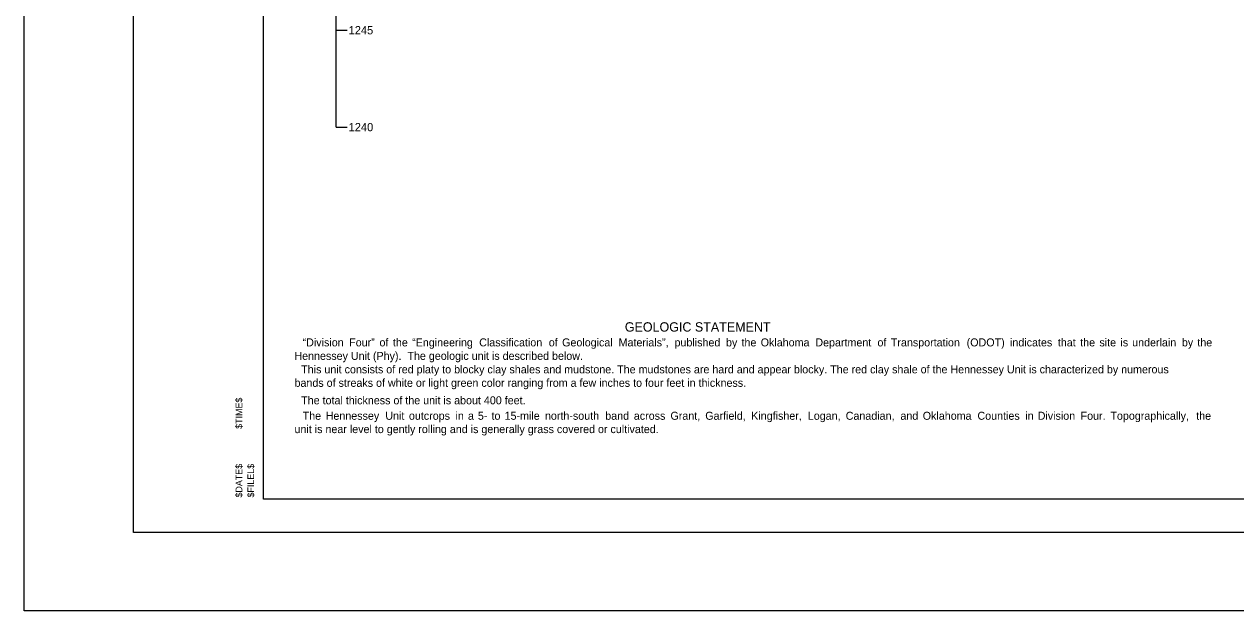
# Model space of a CAD drawing. Extents: x 7 to 126, y 24 to 56.
# Drawn here: x 48.3 to 66.46, y 29.97 to 38.77 of the extents above; entities that cross this region are included whole.
import ezdxf

# ---------------------------------------------------------------- set-up
doc = ezdxf.new("R2010")
doc.units = 0
for name, color, linetype in [('SHT_Plot_Shape_Full', 7, 'Continuous'), ('SHT_Plot_Shape_Half', 7, 'Continuous'), ('SHT_Plot_Stamp', 7, 'Continuous'), ('SHT_Sheet_Border', 7, 'Continuous'), ('Text', 7, 'Continuous')]:
    doc.layers.add(name, color=color, linetype=linetype)

# ---------------------------------------------------------------- blocks, each defined once
blk = doc.blocks.new('Stamp_Plot_Stamp')
at = {"layer": 'SHT_Plot_Stamp'}
for s, p in [('$TIME$', (1.695, 1.572)), ('$DATE$', (1.695, 0.542)), ('$FILEL$', (1.873, 0.542))]:
    blk.add_text(s, height=0.1, rotation=90, dxfattribs=at).set_placement(p)

msp = doc.modelspace()

# ---------------------------------------------------------------- linework, layer by layer
msp.add_line((52.975, 37.223), (52.975, 50.304))
for points in [[(52.975, 38.676), (53.142, 38.676)], [(52.975, 37.223), (53.142, 37.223)]]:
    msp.add_lwpolyline(points)
at = {"layer": 'SHT_Plot_Shape_Full'}
msp.add_lwpolyline([(48.302, 53.971), (84.302, 53.971), (84.302, 29.971), (48.302, 29.971)], close=True, dxfattribs=at)
at = {"layer": 'SHT_Plot_Shape_Half'}
msp.add_lwpolyline([(49.939, 53.146), (83.939, 53.146), (83.939, 31.146), (49.939, 31.146)], close=True, dxfattribs=at)
at = {"layer": 'SHT_Sheet_Border'}
msp.add_lwpolyline([(51.889, 52.646), (83.389, 52.646), (83.389, 31.646), (51.889, 31.646)], close=True, dxfattribs=at)

# ---------------------------------------------------------------- block references
at = {"layer": 'SHT_Plot_Stamp'}
msp.add_blockref('Stamp_Plot_Stamp', (49.875, 31.127), dxfattribs=at)

# ---------------------------------------------------------------- texts
for s, p in [('1245', (53.164, 38.614)), ('1240', (53.164, 37.161))]:
    msp.add_text(s, height=0.124).set_placement(p)
at = {"layer": 'Text'}
for s, height, p in [('GEOLOGIC STATEMENT', 0.14, (57.304, 34.157)), ('“Division', 0.12, (52.474, 33.935)), ('Four”', 0.12, (53.172, 33.935)), ('of', 0.12, (53.627, 33.935)), ('the', 0.12, (53.828, 33.935)), ('“Engineering', 0.12, (54.116, 33.935)), ('Classification', 0.12, (55.121, 33.935)), ('of', 0.12, (56.164, 33.935)), ('Geological', 0.12, (56.364, 33.935)), ('Materials”,', 0.12, (57.211, 33.935)), ('published', 0.12, (58.049, 33.935)), ('by', 0.12, (58.821, 33.935)), ('the', 0.12, (59.053, 33.935)), ('Oklahoma', 0.12, (59.341, 33.935)), ('Department', 0.12, (60.16, 33.935)), ('of', 0.12, (61.091, 33.935)), ('Transportation', 0.12, (61.292, 33.935)), ('(ODOT)', 0.12, (62.428, 33.935)), ('indicates', 0.12, (63.078, 33.935)), ('that', 0.12, (63.795, 33.935)), ('the', 0.12, (64.13, 33.935)), ('site', 0.12, (64.418, 33.935)), ('is', 0.12, (64.733, 33.935)), ('underlain', 0.12, (64.909, 33.935)), ('by', 0.12, (65.654, 33.935)), ('the ', 0.12, (65.886, 33.935)), ('Hennessey Unit (Phy).  The geologic unit is described below.', 0.12, (52.351, 33.733)), ('  This unit consists of red platy to blocky clay shales and mudstone. The mudstones are hard and appear blocky. The red clay shale of the Hennessey Unit is characterized by numerous ', 0.12, (52.364, 33.531)), ('bands of streaks of white or light green color ranging from a few inches to four feet in thickness.', 0.12, (52.353, 33.329)), ('  The total thickness of the unit is about 400 feet.', 0.12, (52.364, 33.067)), ('The', 0.12, (52.475, 32.835)), ('Hennessey', 0.12, (52.82, 32.835)), ('Unit', 0.12, (53.714, 32.835)), ('outcrops', 0.12, (54.068, 32.835)), ('in', 0.12, (54.766, 32.835)), ('a', 0.12, (54.953, 32.835)), ('5-', 0.12, (55.101, 32.835)), ('to', 0.12, (55.306, 32.835)), ('15-mile', 0.12, (55.502, 32.835)), ('north-south', 0.12, (56.107, 32.835)), ('band', 0.12, (57.011, 32.835)), ('across', 0.12, (57.439, 32.835)), ('Grant,', 0.12, (57.988, 32.835)), ('Garfield,', 0.12, (58.51, 32.835)), ('Kingfisher,', 0.12, (59.199, 32.835)), ('Logan,', 0.12, (60.047, 32.835)), ('Canadian,', 0.12, (60.615, 32.835)), ('and', 0.12, (61.435, 32.835)), ('Oklahoma', 0.12, (61.77, 32.835)), ('Counties', 0.12, (62.59, 32.835)), ('in', 0.12, (63.307, 32.835)), ('Division', 0.12, (63.493, 32.835)), ('Four.', 0.12, (64.136, 32.835)), ('Topographically,', 0.12, (64.583, 32.835)), ('the ', 0.12, (65.869, 32.835)), ('unit is near level to gently rolling and is generally grass covered or cultivated.  ', 0.12, (52.353, 32.635))]:
    msp.add_text(s, height=height, dxfattribs=at).set_placement(p)

doc.saveas('drawing.dxf')
